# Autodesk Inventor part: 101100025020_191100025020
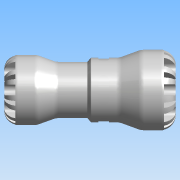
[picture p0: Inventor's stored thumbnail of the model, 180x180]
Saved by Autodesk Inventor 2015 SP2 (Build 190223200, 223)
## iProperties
Created: 2016-12
Part Number: 101100025020_191100025020
Material: PVC-Piping
Description: PLASSON REDUCING COUPLING 25X20 SERIES 1
Document SubType Name: Modeling
Designer: KIM
Mass: 113.204 g
Surface Area: 237.851 cm^2
Volume: 80.8599 cm^3
Density: 1.4 g/cm^3
Appearance: Smooth - White
Author: KIM
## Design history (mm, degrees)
derived "1011.ipt"
feature "Solid1::1011.ipt"
tag "TaggingFeature1"
body "Solid1"
other parameters: "d2" = 20.16, "d3" = 25, "d4" = 47, "d6" = 48, "d7" = 2.08333, "d8" = 41, "d10" = 25, "d11" = 18.9, "d12" = 45, "d13" = 1.66667, "d14" = 37.6, "d15" = 32.8, "d16" = 20 deg, "d17" = 20 deg, "d18" = 130 deg, "d22" = 6.8, "d25" = 6.8, "d26" = 0, "d28" = 360 deg, "d30" = 8 deg, "d31" = 0.5, "d32" = 8 deg, "d33" = 0.5, "d35" = 0, "d37" = 360 deg, "d39" = 6.4, "d42" = 6.4, "d43" = 0, "d45" = 360 deg, "d47" = 0.4, "d48" = 8 deg, "d49" = 8 deg, "d50" = 0.4, "d52" = 0, "d54" = 360 deg, "d56" = 8.2, "d57" = 9.4, "d58" = 0.5, "d60" = 5.64, "d61" = 6.25, "d62" = 11.34, "d63" = 0, "d66" = 0, "d68" = 360 deg, "d75" = 7.26119, "d77" = 36.66, "d78" = 0.47, "d_" = 25, "E_" = 47, "l_" = 48, "E1" = 41, "l1" = 45, "Plasson" = 1, "d20" = 8, "d21" = 8.5, "d23" = 47, "d40" = 41, "d41" = 25, "d59" = 14.52239
